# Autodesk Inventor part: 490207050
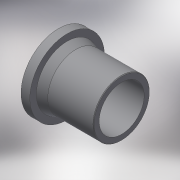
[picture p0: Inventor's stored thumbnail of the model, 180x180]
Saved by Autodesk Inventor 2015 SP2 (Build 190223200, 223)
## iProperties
Created: 2017-07
Part Number: 490207050
Material: Generic
Description: Stub Flange 50
Document SubType Name: Modeling
Designer: Кирилл
Mass: 130.568 g
Surface Area: 403.904 cm^2
Volume: 130.568 cm^3
Density: 1 g/cm^3
Appearance: Default
Author: Кирилл
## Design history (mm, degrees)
derived "490207.ipt"
feature "Solid1::490207.ipt"
tag "TaggingFeature1"
body "Solid1"
other parameters: "d0" = 104, "d1" = 61, "d4" = 88, "d5" = 12, "d6" = 75, "d17" = 1, "d18" = 1, "d19" = 1, "d21" = 1, "d24" = 1, "d25" = 1, "d26" = 0.5, "d27" = 0, "d32" = 0.5, "L_" = 104, "L_1" = 75, "D_" = 88, "D_1" = 61, "a_" = 12
